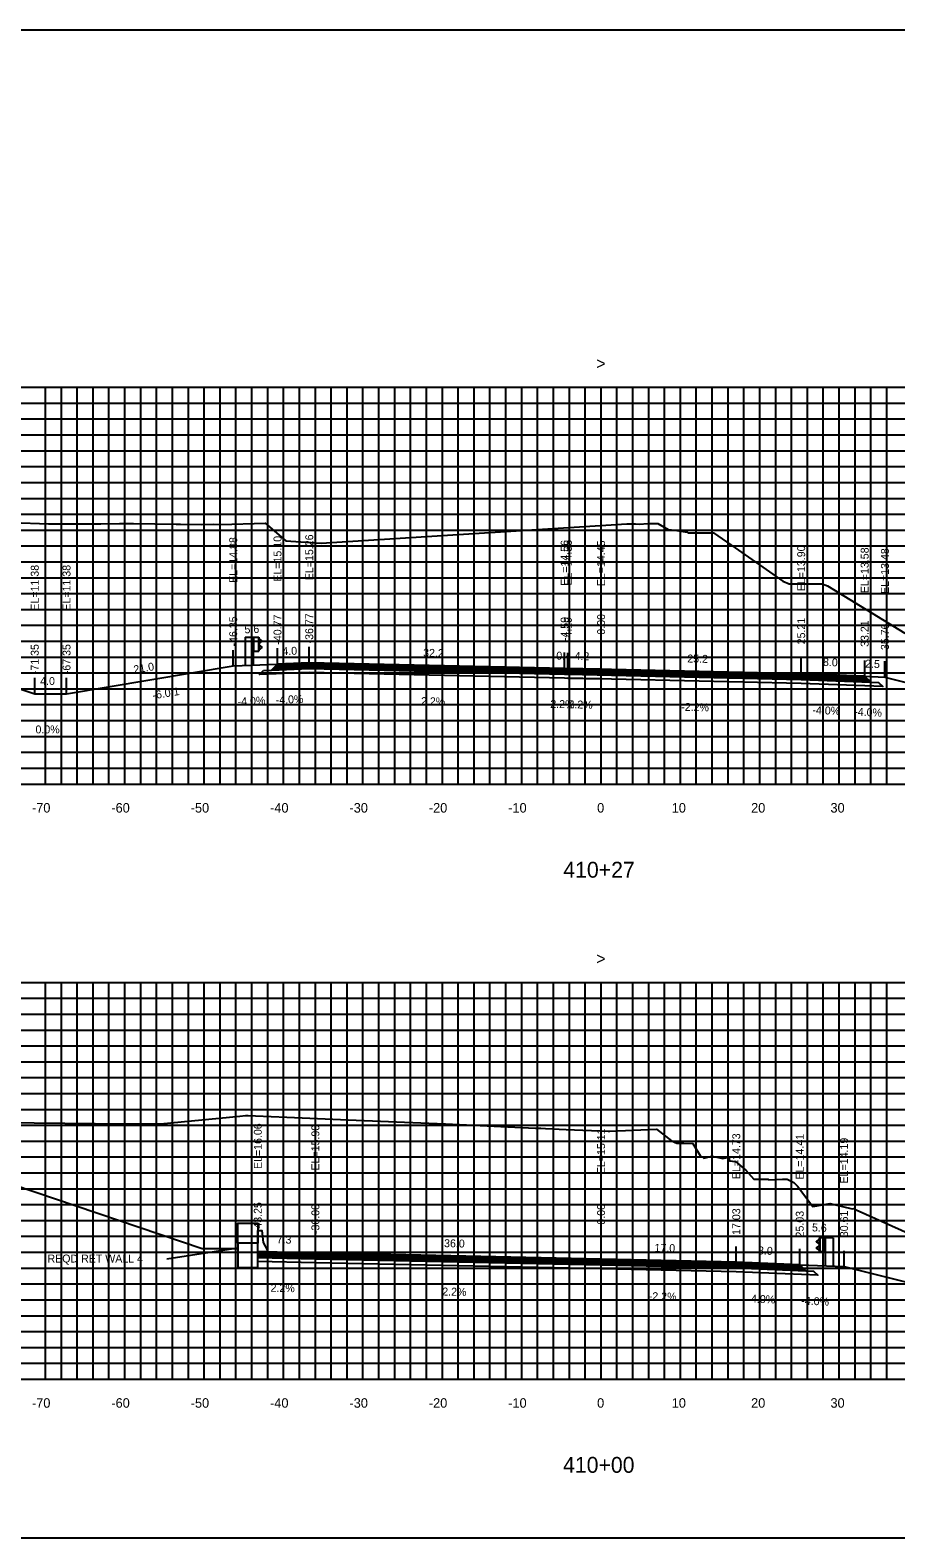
# Model space of a CAD drawing. Extents: x 1800976 to 1805104, y 250057 to 250580.
# Drawn here: x 1804259.1 to 1804368.1, y 250079.4 to 250269.4 of the extents above; entities that cross this region are included whole.
import ezdxf

# ---------------------------------------------------------------- set-up
doc = ezdxf.new("R2010")
doc.units = 0
for name, color, linetype in [('1', 7, 'Continuous'), ('10', 7, 'Continuous'), ('3', 7, 'Continuous'), ('4', 7, 'Continuous'), ('60', 7, 'Continuous'), ('BASE', 7, 'Continuous'), ('CL-CNST', 7, 'Continuous'), ('Default', 7, 'Continuous'), ('Level 1', 7, 'Continuous'), ('Level 62', 7, 'Continuous'), ('LOWER BINDER', 7, 'Continuous'), ('M-ROADS', 7, 'Continuous'), ('UPPER BINDER', 7, 'Continuous'), ('WEARING', 7, 'Continuous')]:
    doc.layers.add(name, color=color, linetype=linetype)

msp = doc.modelspace()

# ---------------------------------------------------------------- linework, layer by layer
for p, q in [((1804284.65, 250189.31), (1804284.65, 250191.31)), ((1804290.23, 250189.54), (1804290.23, 250191.54)), ((1804294.23, 250189.7), (1804294.23, 250191.7)), ((1804326.41, 250188.99), (1804326.41, 250190.99)), ((1804326.81, 250188.98), (1804326.81, 250190.98)), ((1804331, 250188.89), (1804331, 250190.89)), ((1804356.21, 250188.33), (1804356.21, 250190.33)), ((1804364.21, 250188.01), (1804364.21, 250190.01)), ((1804366.76, 250187.91), (1804366.76, 250189.91)), ((1804259.65, 250185.81), (1804259.65, 250187.81)), ((1804263.65, 250185.81), (1804263.65, 250187.81)), ((1804287.75, 250115.49), (1804287.75, 250117.49)), ((1804295, 250115.33), (1804295, 250117.33)), ((1804331, 250114.54), (1804331, 250116.54)), ((1804348.03, 250114.16), (1804348.03, 250116.16)), ((1804356.03, 250113.84), (1804356.03, 250115.84)), ((1804361.61, 250113.62), (1804361.61, 250115.62))]:
    msp.add_line(p, q)
msp.add_lwpolyline([(1804181, 250079.43), (1804481, 250079.43), (1804481, 250269.43), (1804181, 250269.43)], close=True)
at = {"layer": '3'}
msp.add_line((1804276.29, 250114.59), (1804285.25, 250115.96), dxfattribs=at)
at = {"layer": '60'}
for p, q in [((1804181, 250174.43), (1804481, 250174.43)), ((1804261, 250174.37), (1804261, 250174.43)), ((1804271, 250174.37), (1804271, 250174.43)), ((1804281, 250174.37), (1804281, 250174.43)), ((1804291, 250174.37), (1804291, 250174.43)), ((1804301, 250174.37), (1804301, 250174.43)), ((1804311, 250174.37), (1804311, 250174.43)), ((1804321, 250174.37), (1804321, 250174.43)), ((1804331, 250174.37), (1804331, 250174.43)), ((1804341, 250174.37), (1804341, 250174.43)), ((1804351, 250174.37), (1804351, 250174.43)), ((1804361, 250174.37), (1804361, 250174.43)), ((1804181, 250099.43), (1804481, 250099.43)), ((1804261, 250099.37), (1804261, 250099.43)), ((1804271, 250099.37), (1804271, 250099.43)), ((1804281, 250099.37), (1804281, 250099.43)), ((1804291, 250099.37), (1804291, 250099.43)), ((1804301, 250099.37), (1804301, 250099.43)), ((1804311, 250099.37), (1804311, 250099.43)), ((1804321, 250099.37), (1804321, 250099.43)), ((1804331, 250099.37), (1804331, 250099.43)), ((1804341, 250099.37), (1804341, 250099.43)), ((1804351, 250099.37), (1804351, 250099.43)), ((1804361, 250099.37), (1804361, 250099.43))]:
    msp.add_line(p, q, dxfattribs=at)
at = {"layer": 'BASE'}
for points in [[(1804288.48, 250188.75), (1804289.48, 250188.79), (1804294.23, 250188.98), (1804326.41, 250188.27), (1804331, 250188.17), (1804326.82, 250188.26), (1804356.22, 250187.61), (1804364.96, 250187.26), (1804365.96, 250187.22), (1804366.48, 250186.7), (1804356.22, 250187.11), (1804326.82, 250187.76), (1804331, 250187.67), (1804326.41, 250187.77), (1804294.23, 250188.48), (1804287.96, 250188.22)], [(1804287.75, 250114.77), (1804295, 250114.61), (1804331, 250113.82), (1804348.03, 250113.44), (1804356.78, 250113.09), (1804357.78, 250113.05), (1804358.3, 250112.53), (1804348.03, 250112.94), (1804331, 250113.32), (1804295, 250114.11), (1804287.75, 250114.27)]]:
    msp.add_lwpolyline(points, close=True, dxfattribs=at)
at = {"layer": 'CL-CNST'}
msp.add_line((1804280.75, 250115.88), (1804285.25, 250115.88), dxfattribs=at)
for points in [[(1804198.7, 250206.13), (1804259.65, 250185.81), (1804263.65, 250185.81), (1804284.65, 250189.31), (1804290.23, 250189.54), (1804294.23, 250189.7), (1804326.41, 250188.99), (1804326.81, 250188.98), (1804331, 250188.89), (1804356.21, 250188.33), (1804364.21, 250188.01), (1804366.76, 250187.91), (1804390.76, 250181.91), (1804394.76, 250181.91), (1804405.91, 250184.7)], [(1804227.18, 250134.02), (1804227.88, 250133.78), (1804280.75, 250115.88), (1804282.94, 250115.88), (1804285.24, 250115.88)], [(1804287.75, 250115.49), (1804295, 250115.33), (1804331, 250114.54), (1804348.03, 250114.16), (1804356.03, 250113.84), (1804361.61, 250113.62), (1804385.61, 250107.62), (1804389.61, 250107.62), (1804399.28, 250110.04)]]:
    msp.add_lwpolyline(points, dxfattribs=at)
for points in [[(1804287.75, 250116.57), (1804285.25, 250116.57), (1804285.25, 250119.07), (1804287.75, 250119.07)], [(1804285.25, 250113.49), (1804287.75, 250113.49), (1804287.75, 250116.57), (1804285.25, 250116.57)]]:
    msp.add_lwpolyline(points, close=True, dxfattribs=at)
at = {"layer": 'Default'}
msp.add_line((1804287.75, 250115.49), (1804287.75, 250118.16), dxfattribs=at)
msp.add_lwpolyline([(1804287.75, 250118.16), (1804288.25, 250118.16), (1804288.43, 250116.66), (1804288.98, 250115.66), (1804289, 250115.49), (1804287.75, 250115.49)], dxfattribs=at)
at = {"layer": 'Level 1'}
for p, q in [((1804286.15, 250192.94), (1804286.15, 250189.37)), ((1804286.15, 250192.94), (1804287.9, 250192.94)), ((1804287.15, 250192.94), (1804287.15, 250189.41)), ((1804287.2, 250192.94), (1804287.2, 250191.19)), ((1804287.85, 250192.94), (1804287.85, 250191.19)), ((1804287.9, 250192.94), (1804287.9, 250191.19)), ((1804287.9, 250192.79), (1804288.27, 250192.49)), ((1804288.27, 250192.42), (1804287.9, 250192.13)), ((1804287.15, 250191.19), (1804287.9, 250191.19)), ((1804287.9, 250191.99), (1804288.27, 250191.69)), ((1804288.27, 250191.62), (1804287.9, 250191.34)), ((1804358.49, 250117.09), (1804358.13, 250116.79)), ((1804358.13, 250116.72), (1804358.49, 250116.43)), ((1804358.49, 250116.29), (1804358.13, 250116)), ((1804358.49, 250117.24), (1804358.49, 250115.49)), ((1804360.24, 250117.24), (1804358.49, 250117.24)), ((1804358.54, 250117.24), (1804358.54, 250115.49)), ((1804359.19, 250117.24), (1804359.19, 250115.49)), ((1804359.24, 250117.24), (1804359.24, 250113.71)), ((1804360.24, 250117.24), (1804360.24, 250113.67)), ((1804358.13, 250115.92), (1804358.49, 250115.64)), ((1804359.24, 250115.49), (1804358.49, 250115.49))]:
    msp.add_line(p, q, dxfattribs=at)
for centre, start, end in [((1804288.23, 250192.45), 313.3792, 45), ((1804288.23, 250191.66), 313.3792, 45), ((1804358.16, 250116.76), 135, 226.6208), ((1804358.16, 250115.96), 135, 226.6208)]:
    msp.add_arc(centre, 0.05, start, end, dxfattribs=at)
at = {"layer": 'Level 62'}
for p, q in [((1804181, 250224.43), (1804481, 250224.43)), ((1804261, 250174.43), (1804261, 250224.43)), ((1804263, 250174.43), (1804263, 250224.43)), ((1804265, 250174.43), (1804265, 250224.43)), ((1804267, 250174.43), (1804267, 250224.43)), ((1804269, 250174.43), (1804269, 250224.43)), ((1804271, 250174.43), (1804271, 250224.43)), ((1804273, 250174.43), (1804273, 250224.43)), ((1804275, 250174.43), (1804275, 250224.43)), ((1804277, 250174.43), (1804277, 250224.43)), ((1804279, 250174.43), (1804279, 250224.43)), ((1804281, 250174.43), (1804281, 250224.43)), ((1804283, 250174.43), (1804283, 250224.43)), ((1804285, 250174.43), (1804285, 250224.43)), ((1804287, 250174.43), (1804287, 250224.43)), ((1804289, 250174.43), (1804289, 250224.43)), ((1804291, 250174.43), (1804291, 250224.43)), ((1804293, 250174.43), (1804293, 250224.43)), ((1804295, 250174.43), (1804295, 250224.43)), ((1804297, 250174.43), (1804297, 250224.43)), ((1804299, 250174.43), (1804299, 250224.43)), ((1804301, 250174.43), (1804301, 250224.43)), ((1804303, 250174.43), (1804303, 250224.43)), ((1804305, 250174.43), (1804305, 250224.43)), ((1804307, 250174.43), (1804307, 250224.43)), ((1804309, 250174.43), (1804309, 250224.43)), ((1804311, 250174.43), (1804311, 250224.43)), ((1804313, 250174.43), (1804313, 250224.43)), ((1804315, 250174.43), (1804315, 250224.43)), ((1804317, 250174.43), (1804317, 250224.43)), ((1804319, 250174.43), (1804319, 250224.43)), ((1804321, 250174.43), (1804321, 250224.43)), ((1804323, 250174.43), (1804323, 250224.43)), ((1804325, 250174.43), (1804325, 250224.43)), ((1804327, 250174.43), (1804327, 250224.43)), ((1804329, 250174.43), (1804329, 250224.43)), ((1804331, 250174.43), (1804331, 250224.43)), ((1804333, 250174.43), (1804333, 250224.43)), ((1804335, 250174.43), (1804335, 250224.43)), ((1804337, 250174.43), (1804337, 250224.43)), ((1804339, 250174.43), (1804339, 250224.43)), ((1804341, 250174.43), (1804341, 250224.43)), ((1804343, 250174.43), (1804343, 250224.43)), ((1804345, 250174.43), (1804345, 250224.43)), ((1804347, 250174.43), (1804347, 250224.43)), ((1804349, 250174.43), (1804349, 250224.43)), ((1804351, 250174.43), (1804351, 250224.43)), ((1804353, 250174.43), (1804353, 250224.43)), ((1804355, 250174.43), (1804355, 250224.43)), ((1804357, 250174.43), (1804357, 250224.43)), ((1804359, 250174.43), (1804359, 250224.43)), ((1804361, 250174.43), (1804361, 250224.43)), ((1804363, 250174.43), (1804363, 250224.43)), ((1804365, 250174.43), (1804365, 250224.43)), ((1804367, 250174.43), (1804367, 250224.43)), ((1804181, 250222.43), (1804481, 250222.43)), ((1804181, 250220.43), (1804481, 250220.43)), ((1804181, 250218.43), (1804481, 250218.43)), ((1804181, 250216.43), (1804481, 250216.43)), ((1804181, 250214.43), (1804481, 250214.43)), ((1804181, 250212.43), (1804481, 250212.43)), ((1804181, 250210.43), (1804481, 250210.43)), ((1804181, 250208.43), (1804481, 250208.43)), ((1804181, 250206.43), (1804481, 250206.43)), ((1804181, 250204.43), (1804481, 250204.43)), ((1804181, 250202.43), (1804481, 250202.43)), ((1804181, 250200.43), (1804481, 250200.43)), ((1804181, 250198.43), (1804481, 250198.43)), ((1804181, 250196.43), (1804481, 250196.43)), ((1804181, 250194.43), (1804481, 250194.43)), ((1804181, 250192.43), (1804481, 250192.43)), ((1804181, 250190.43), (1804481, 250190.43)), ((1804181, 250188.43), (1804481, 250188.43)), ((1804181, 250186.43), (1804481, 250186.43)), ((1804181, 250184.43), (1804481, 250184.43)), ((1804181, 250182.43), (1804481, 250182.43)), ((1804181, 250180.43), (1804481, 250180.43)), ((1804181, 250178.43), (1804481, 250178.43)), ((1804181, 250176.43), (1804481, 250176.43)), ((1804181, 250174.43), (1804481, 250174.43)), ((1804181, 250149.43), (1804481, 250149.43)), ((1804261, 250099.43), (1804261, 250149.43)), ((1804263, 250099.43), (1804263, 250149.43)), ((1804265, 250099.43), (1804265, 250149.43)), ((1804267, 250099.43), (1804267, 250149.43)), ((1804269, 250099.43), (1804269, 250149.43)), ((1804271, 250099.43), (1804271, 250149.43)), ((1804273, 250099.43), (1804273, 250149.43)), ((1804275, 250099.43), (1804275, 250149.43)), ((1804277, 250099.43), (1804277, 250149.43)), ((1804279, 250099.43), (1804279, 250149.43)), ((1804281, 250099.43), (1804281, 250149.43)), ((1804283, 250099.43), (1804283, 250149.43)), ((1804285, 250099.43), (1804285, 250149.43)), ((1804287, 250099.43), (1804287, 250149.43)), ((1804289, 250099.43), (1804289, 250149.43)), ((1804291, 250099.43), (1804291, 250149.43)), ((1804293, 250099.43), (1804293, 250149.43)), ((1804295, 250099.43), (1804295, 250149.43)), ((1804297, 250099.43), (1804297, 250149.43)), ((1804299, 250099.43), (1804299, 250149.43)), ((1804301, 250099.43), (1804301, 250149.43)), ((1804303, 250099.43), (1804303, 250149.43)), ((1804305, 250099.43), (1804305, 250149.43)), ((1804307, 250099.43), (1804307, 250149.43)), ((1804309, 250099.43), (1804309, 250149.43)), ((1804311, 250099.43), (1804311, 250149.43)), ((1804313, 250099.43), (1804313, 250149.43)), ((1804315, 250099.43), (1804315, 250149.43)), ((1804317, 250099.43), (1804317, 250149.43)), ((1804319, 250099.43), (1804319, 250149.43)), ((1804321, 250099.43), (1804321, 250149.43)), ((1804323, 250099.43), (1804323, 250149.43)), ((1804325, 250099.43), (1804325, 250149.43)), ((1804327, 250099.43), (1804327, 250149.43)), ((1804329, 250099.43), (1804329, 250149.43)), ((1804331, 250099.43), (1804331, 250149.43)), ((1804333, 250099.43), (1804333, 250149.43)), ((1804335, 250099.43), (1804335, 250149.43)), ((1804337, 250099.43), (1804337, 250149.43)), ((1804339, 250099.43), (1804339, 250149.43)), ((1804341, 250099.43), (1804341, 250149.43)), ((1804343, 250099.43), (1804343, 250149.43)), ((1804345, 250099.43), (1804345, 250149.43)), ((1804347, 250099.43), (1804347, 250149.43)), ((1804349, 250099.43), (1804349, 250149.43)), ((1804351, 250099.43), (1804351, 250149.43)), ((1804353, 250099.43), (1804353, 250149.43)), ((1804355, 250099.43), (1804355, 250149.43)), ((1804357, 250099.43), (1804357, 250149.43)), ((1804359, 250099.43), (1804359, 250149.43)), ((1804361, 250099.43), (1804361, 250149.43)), ((1804363, 250099.43), (1804363, 250149.43)), ((1804365, 250099.43), (1804365, 250149.43)), ((1804367, 250099.43), (1804367, 250149.43)), ((1804181, 250147.43), (1804481, 250147.43)), ((1804181, 250145.43), (1804481, 250145.43)), ((1804181, 250143.43), (1804481, 250143.43)), ((1804181, 250141.43), (1804481, 250141.43)), ((1804181, 250139.43), (1804481, 250139.43)), ((1804181, 250137.43), (1804481, 250137.43)), ((1804181, 250135.43), (1804481, 250135.43)), ((1804181, 250133.43), (1804481, 250133.43)), ((1804181, 250131.43), (1804481, 250131.43)), ((1804181, 250129.43), (1804481, 250129.43)), ((1804181, 250127.43), (1804481, 250127.43)), ((1804181, 250125.43), (1804481, 250125.43)), ((1804181, 250123.43), (1804481, 250123.43)), ((1804181, 250121.43), (1804481, 250121.43)), ((1804181, 250119.43), (1804481, 250119.43)), ((1804181, 250117.43), (1804481, 250117.43)), ((1804181, 250115.43), (1804481, 250115.43)), ((1804181, 250113.43), (1804481, 250113.43)), ((1804181, 250111.43), (1804481, 250111.43)), ((1804181, 250109.43), (1804481, 250109.43)), ((1804181, 250107.43), (1804481, 250107.43)), ((1804181, 250105.43), (1804481, 250105.43)), ((1804181, 250103.43), (1804481, 250103.43)), ((1804181, 250101.43), (1804481, 250101.43)), ((1804181, 250099.43), (1804481, 250099.43))]:
    msp.add_line(p, q, dxfattribs=at)
at = {"layer": 'LOWER BINDER'}
for points in [[(1804294.23, 250189.17), (1804326.41, 250188.46), (1804331, 250188.36), (1804326.81, 250188.45), (1804356.22, 250187.8), (1804364.77, 250187.46), (1804364.96, 250187.26), (1804356.22, 250187.61), (1804326.82, 250188.26), (1804331, 250188.17), (1804326.41, 250188.27), (1804294.23, 250188.98), (1804289.48, 250188.79), (1804289.68, 250188.98)], [(1804294.23, 250189.36), (1804326.41, 250188.65), (1804331, 250188.55), (1804326.81, 250188.64), (1804356.21, 250187.99), (1804364.57, 250187.66), (1804364.77, 250187.46), (1804356.22, 250187.8), (1804326.81, 250188.45), (1804331, 250188.36), (1804326.41, 250188.46), (1804294.23, 250189.17), (1804289.68, 250188.98), (1804289.88, 250189.18)], [(1804295, 250114.99), (1804331, 250114.2), (1804348.03, 250113.82), (1804356.38, 250113.49), (1804356.58, 250113.29), (1804348.03, 250113.63), (1804331, 250114.01), (1804295, 250114.8), (1804287.75, 250114.96), (1804287.75, 250115.15)], [(1804295, 250114.8), (1804331, 250114.01), (1804348.03, 250113.63), (1804356.58, 250113.29), (1804356.78, 250113.09), (1804348.03, 250113.44), (1804331, 250113.82), (1804295, 250114.61), (1804287.75, 250114.77), (1804287.75, 250114.96)]]:
    msp.add_lwpolyline(points, close=True, dxfattribs=at)
at = {"layer": 'M-ROADS'}
for points in [[(1804256.82, 250207.38), (1804261.4, 250207.23), (1804261.57, 250207.21), (1804267.99, 250207.23), (1804270.31, 250207.26), (1804272.07, 250207.28), (1804277.48, 250207.18), (1804278.03, 250207.16), (1804280.7, 250207.14), (1804282.11, 250207.17), (1804283.08, 250207.12), (1804288.69, 250207.3), (1804291.28, 250205.06), (1804295.74, 250204.79), (1804334.26, 250207.21), (1804335.33, 250207.2), (1804335.8, 250207.17), (1804336.93, 250207.24), (1804338.15, 250207.24), (1804339.44, 250206.5), (1804340.29, 250206.42), (1804341.83, 250206.18), (1804341.96, 250206.1), (1804342.69, 250206.1), (1804343.95, 250206.1), (1804345.16, 250206.1), (1804347.88, 250204.19), (1804353.88, 250200.01), (1804354.69, 250199.67), (1804356.69, 250199.67), (1804357.2, 250199.67), (1804358.87, 250199.67), (1804359.51, 250199.42), (1804369.28, 250193.46)], [(1804238.43, 250132.02), (1804259.59, 250131.75), (1804271.11, 250131.62), (1804275.5, 250131.59), (1804285.49, 250132.59), (1804286.2, 250132.66), (1804286.54, 250132.65), (1804287.46, 250132.61), (1804291.4, 250132.44), (1804299.14, 250132.1), (1804309.3, 250131.68), (1804311.39, 250131.59), (1804313.17, 250131.51), (1804322.74, 250131.08), (1804323.39, 250131.05), (1804323.99, 250131.01), (1804326.6, 250130.9), (1804331.88, 250130.68), (1804332.11, 250130.69), (1804337.98, 250130.95), (1804339.86, 250129.48), (1804340.53, 250129.16), (1804341.42, 250129.15), (1804342.55, 250129.14), (1804343.54, 250127.52), (1804343.74, 250127.44), (1804343.94, 250127.27), (1804344.97, 250127.52), (1804345.79, 250127.35), (1804346.36, 250127.23), (1804347.08, 250127.41), (1804347.19, 250126.93), (1804347.94, 250126.87), (1804349.22, 250125.76), (1804350.26, 250124.63), (1804352.01, 250124.63), (1804352.15, 250124.56), (1804353.86, 250124.63), (1804354.44, 250124.63), (1804355.27, 250124.2), (1804355.76, 250123.76), (1804357.67, 250121.17), (1804359.88, 250121.55), (1804360.19, 250121.48), (1804362.65, 250120.89), (1804362.84, 250120.93), (1804363.13, 250120.77), (1804373.33, 250116.2)]]:
    msp.add_lwpolyline(points, dxfattribs=at)
at = {"layer": 'UPPER BINDER'}
for points in [[(1804356.21, 250187.99), (1804364.57, 250187.66), (1804364.37, 250187.86), (1804356.21, 250188.18), (1804326.81, 250188.83), (1804331, 250188.74), (1804326.41, 250188.84), (1804294.23, 250189.55), (1804290.07, 250189.38), (1804289.88, 250189.18), (1804294.23, 250189.36), (1804326.41, 250188.65), (1804331, 250188.55), (1804326.81, 250188.64)], [(1804348.03, 250113.82), (1804356.38, 250113.49), (1804356.19, 250113.69), (1804348.03, 250114.01), (1804331, 250114.39), (1804295, 250115.18), (1804287.75, 250115.34), (1804287.75, 250115.15), (1804295, 250114.99), (1804331, 250114.2)]]:
    msp.add_lwpolyline(points, close=True, dxfattribs=at)
at = {"layer": 'WEARING'}
for points in [[(1804356.21, 250188.18), (1804364.37, 250187.86), (1804364.21, 250188.01), (1804356.21, 250188.33), (1804326.81, 250188.98), (1804331, 250188.89), (1804326.41, 250188.99), (1804294.23, 250189.7), (1804290.23, 250189.54), (1804290.07, 250189.38), (1804294.23, 250189.55), (1804326.41, 250188.84), (1804331, 250188.74), (1804326.81, 250188.83)], [(1804348.03, 250114.01), (1804356.19, 250113.69), (1804356.03, 250113.84), (1804348.03, 250114.16), (1804331, 250114.54), (1804295, 250115.33), (1804287.75, 250115.49), (1804287.75, 250115.34), (1804295, 250115.18), (1804331, 250114.39)]]:
    msp.add_lwpolyline(points, close=True, dxfattribs=at)

# ---------------------------------------------------------------- texts
msp.add_text('-6.0:1', height=1, rotation=9.4623).set_placement((1804274.56, 250185.1))
at = {"layer": '1'}
for s, p in [('410+27', (1804326.24, 250162.63)), ('410+00', (1804326.21, 250087.63))]:
    msp.add_text(s, height=2, dxfattribs=at).set_placement(p)
at = {"layer": '10'}
for s, p in [('-70', (1804259.3, 250170.83)), ('-60', (1804269.3, 250170.83)), ('-50', (1804279.3, 250170.83)), ('-40', (1804289.3, 250170.83)), ('-30', (1804299.3, 250170.83)), ('-20', (1804309.3, 250170.83)), ('-10', (1804319.3, 250170.83)), ('0', (1804330.5, 250170.83)), ('10', (1804339.9, 250170.83)), ('20', (1804349.9, 250170.83)), ('30', (1804359.9, 250170.83)), ('-70', (1804259.3, 250095.83)), ('-60', (1804269.3, 250095.83)), ('-50', (1804279.3, 250095.83)), ('-40', (1804289.3, 250095.83)), ('-30', (1804299.3, 250095.83)), ('-20', (1804309.3, 250095.83)), ('-10', (1804319.3, 250095.83)), ('0', (1804330.5, 250095.83)), ('10', (1804339.9, 250095.83)), ('20', (1804349.9, 250095.83)), ('30', (1804359.9, 250095.83))]:
    msp.add_text(s, height=1.2, dxfattribs=at).set_placement(p)
at = {"layer": '3'}
for s, p in [('EL=14.88', (1804285.15, 250199.78)), ('EL=15.10', (1804290.73, 250199.93)), ('EL=15.26', (1804294.73, 250200.12)), ('EL=14.56', (1804326.91, 250199.41)), ('EL=14.55', (1804327.31, 250199.45)), ('EL=14.45', (1804331.5, 250199.36)), ('EL=13.90', (1804356.71, 250198.73)), ('EL=13.58', (1804364.71, 250198.48)), ('EL=13.48', (1804367.26, 250198.38)), ('EL=11.38', (1804260.15, 250196.28)), ('EL=11.38', (1804264.15, 250196.28)), ('-36.77', (1804294.73, 250192.15)), ('-46.35', (1804285.15, 250191.77)), ('-40.77', (1804290.73, 250191.99)), ('-4.59', (1804326.91, 250192.44)), ('-4.19', (1804327.31, 250192.43)), ('0.00', (1804331.5, 250193.25)), ('25.21', (1804356.71, 250192.03)), ('33.21', (1804364.71, 250191.71)), ('35.76', (1804367.26, 250191.31)), ('-71.35', (1804260.15, 250188.27)), ('-67.35', (1804264.15, 250188.27)), ('EL=16.06', (1804288.25, 250125.91)), ('EL=15.90', (1804295.5, 250125.72)), ('EL=15.11', (1804331.5, 250125.26)), ('EL=14.73', (1804348.53, 250124.64)), ('EL=14.41', (1804356.53, 250124.57)), ('EL=14.19', (1804362.11, 250124.09)), ('-43.25', (1804288.25, 250117.95)), ('-36.00', (1804295.5, 250117.71)), ('0.00', (1804331.5, 250118.9)), ('17.03', (1804348.53, 250117.61)), ('25.03', (1804356.53, 250117.29)), ('30.61', (1804362.11, 250117.32))]:
    msp.add_text(s, height=1, rotation=90, dxfattribs=at).set_placement(p)
msp.add_text('REQD RET WALL 4', height=1, dxfattribs=at).set_placement((1804261.25, 250114.13))
at = {"layer": '4'}
for s, rotation, p in [('5.6', 2.2906, (1804286.09, 250193.41)), ('4.0', 2.2906, (1804290.86, 250190.66)), ('32.2', 358.7397, (1804308.57, 250190.48)), ('0.4', 358.7397, (1804325.35, 250190.11)), ('4.2', 358.7397, (1804327.65, 250190.06)), ('25.2', 358.7397, (1804341.85, 250189.75)), ('8.0', 357.7094, (1804358.94, 250189.32)), ('2.5', 357.7094, (1804364.25, 250189.11)), ('21.0', 9.4623, (1804272.18, 250188.35)), ('-4.0%', 2.2906, (1804285.23, 250184.33)), ('-4.0%', 2.2906, (1804290.02, 250184.52)), ('2.2%', 358.7397, (1804308.3, 250184.38)), ('2.2%', 358.7397, (1804324.59, 250184.03)), ('2.2%', 358.7397, (1804326.88, 250183.98)), ('-2.2%', 358.7397, (1804341.09, 250183.66)), ('-4.0%', 357.7094, (1804357.61, 250183.27)), ('-4.0%', 357.7094, (1804362.88, 250183.06)), ('5.6', 357.7094, (1804357.56, 250118.06)), ('7.3', 358.7397, (1804290.12, 250116.54)), ('36.0', 358.7397, (1804311.21, 250116.07)), ('17.0', 358.7397, (1804337.72, 250115.49)), ('8.0', 357.7094, (1804350.75, 250115.16)), ('2.2%', 358.7397, (1804289.35, 250110.45)), ('2.2%', 358.7397, (1804310.98, 250109.98)), ('-2.2%', 358.7397, (1804337, 250109.4)), ('-4.0%', 357.7094, (1804349.42, 250109.1)), ('-4.0%', 357.7094, (1804356.21, 250108.83))]:
    msp.add_text(s, height=1, rotation=rotation, dxfattribs=at).set_placement(p)
for s, p in [('4.0', (1804260.33, 250186.91)), ('0.0%', (1804259.74, 250180.81))]:
    msp.add_text(s, height=1, dxfattribs=at).set_placement(p)
at = {"layer": '60'}
for p in [(1804330.39, 250226.68), (1804330.39, 250151.68)]:
    msp.add_text('>', height=1.5, dxfattribs=at).set_placement(p)

doc.saveas('drawing.dxf')
